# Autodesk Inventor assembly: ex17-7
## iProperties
Shininess: 64.0
Length Units: 11272
Angle Units: 11279
Time Units: 11290
Mass Units: 11286
Length Display Precision: 3
Angle Display Precision: 2
Compacted: True
Part Number: ex17-7
Document SubType Name: Weldment
Created: 2002-11
Designer: E. MOSS
Density: 0.0
Volumn: 0.0
Area: 0.0
PropertySet Name: Model Information
Control State: 0
Master: False
Checked Out: False
Author: E. MOSS
